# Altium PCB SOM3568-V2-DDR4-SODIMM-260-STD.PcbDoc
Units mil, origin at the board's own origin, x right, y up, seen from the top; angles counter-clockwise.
Board outline 6000 x 4000 mil, 4 copper layers (TOP, VCC, GND, BOTTOM), stack 28.8 mil thick; 1 components, 546 nets, 266 pads, 0 vias.
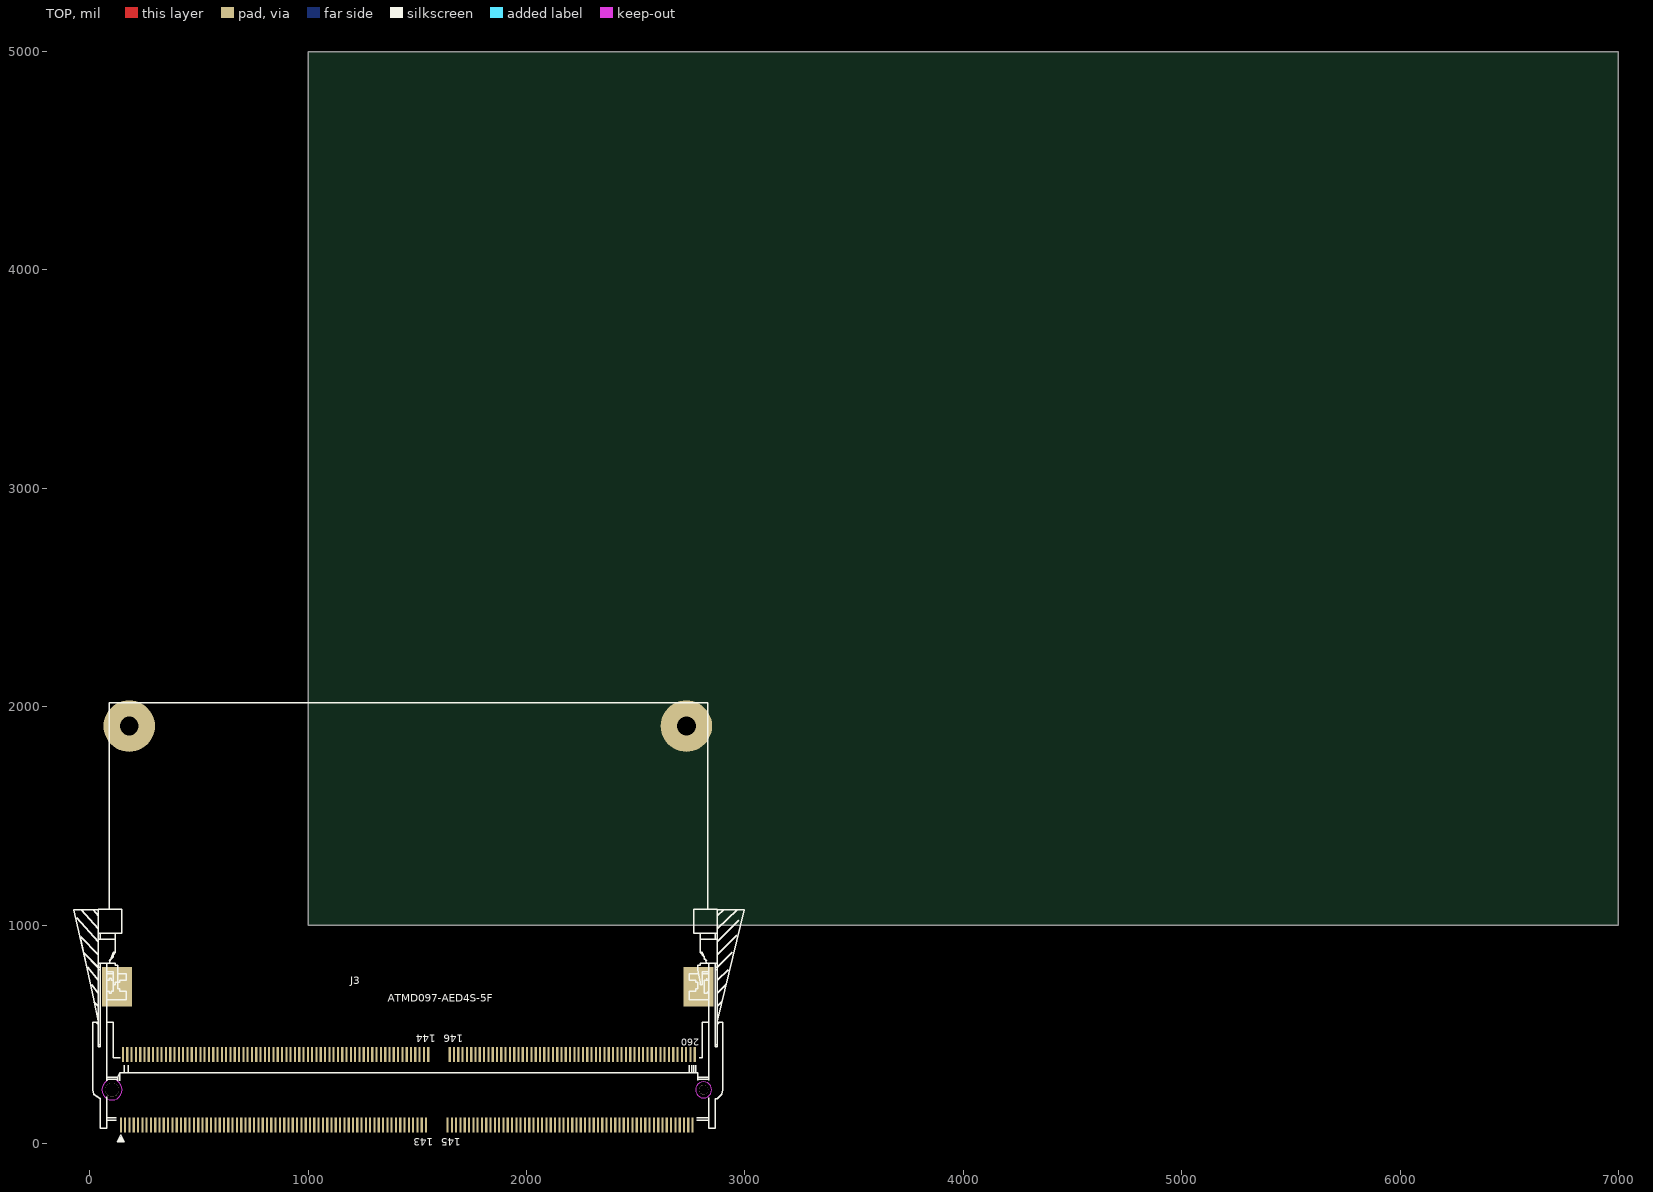
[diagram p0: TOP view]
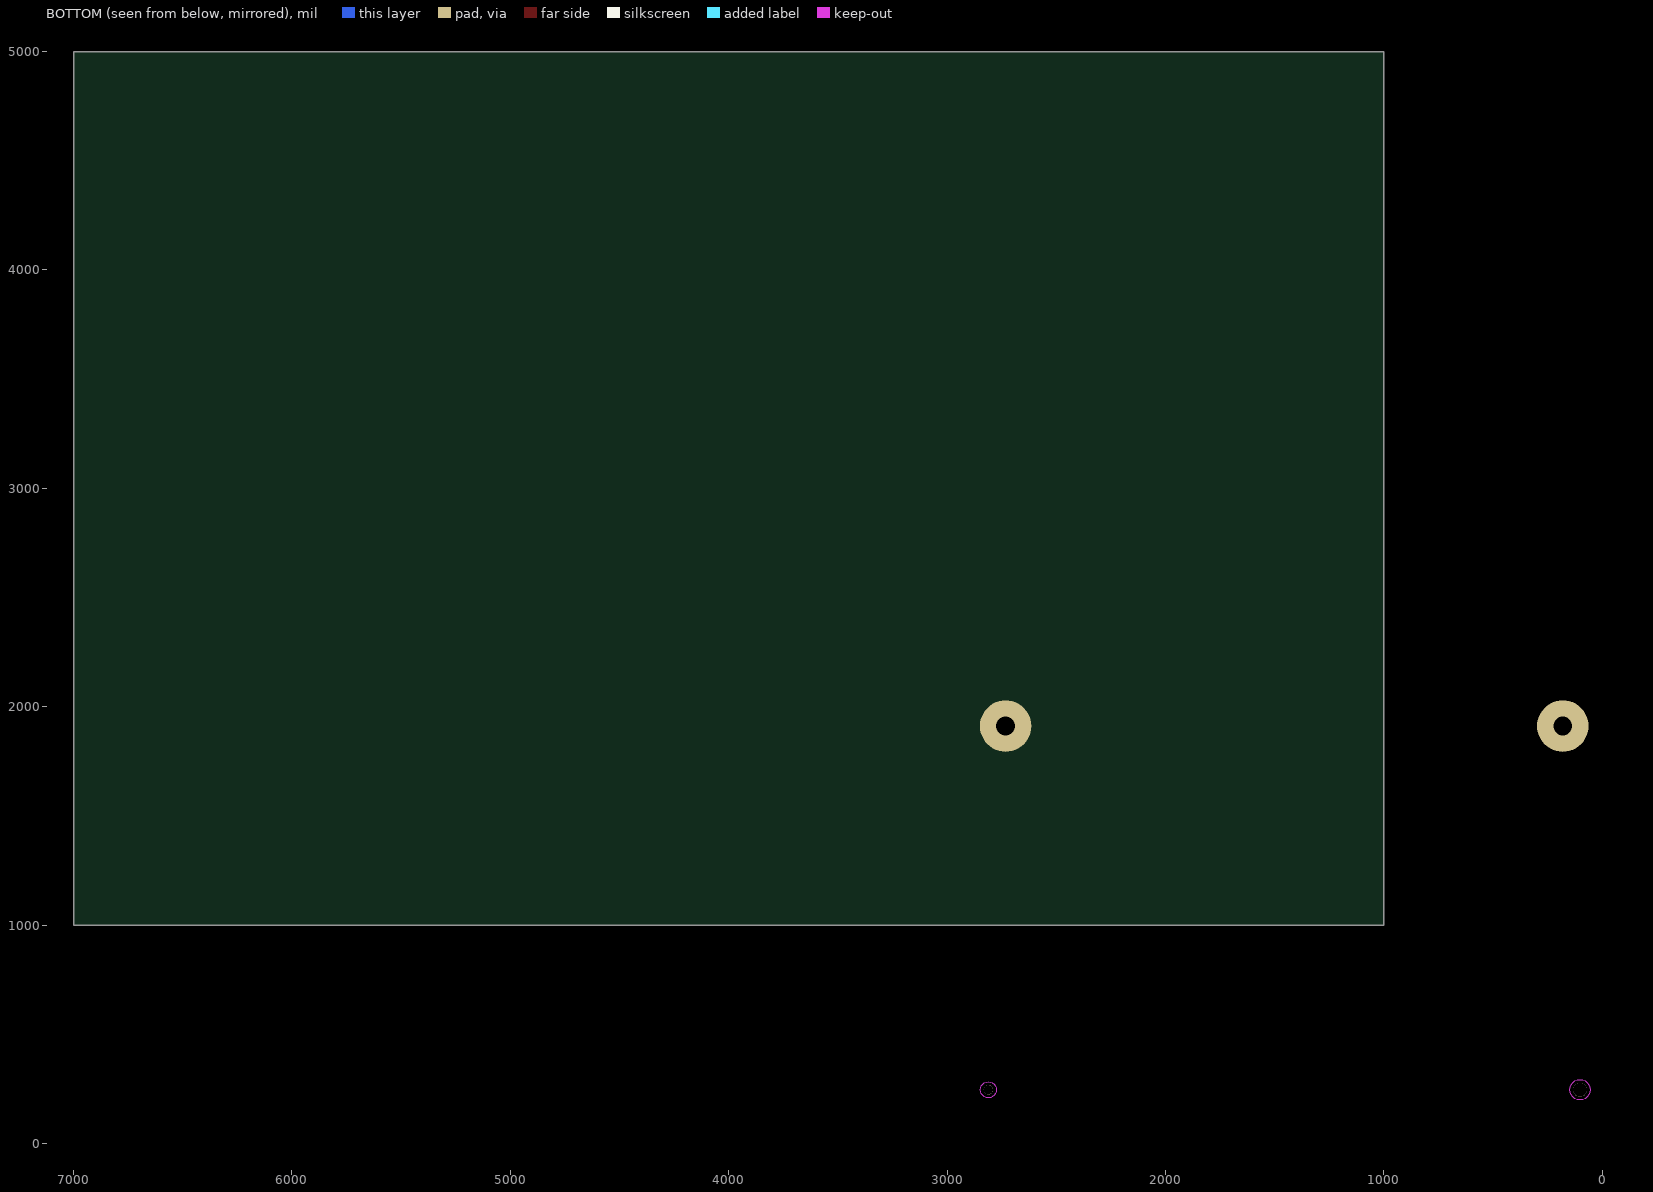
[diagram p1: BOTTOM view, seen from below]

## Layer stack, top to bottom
Top Solder: solder mask 0.4, Solder Resist, Dk 3.5
TOP: signal copper 1.2
Dielectric 1: core 8, FR-4, Dk 4.5
VCC: signal copper 1.2
Dielectric2: core 8, FR-4, Dk 4.5
GND: signal copper 1.2
Dielectric3: core 8, FR-4, Dk 4.5
BOTTOM: signal copper 1.2
Bottom Solder: solder mask 0.4, Solder Resist, Dk 3.5

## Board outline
1000,1000 7000,1000 7000,5000 1000,5000

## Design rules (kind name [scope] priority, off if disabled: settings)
Clearance [All] p1: gap=10 ignorepadtopadclearanceinfootprint=FALSE except(0: Arc-Hole Track-Hole SMDPad-Hole THPad-Hole Via-Hole Fill-Hole Poly-Hole Region-Hole Text-Hole)
DiffPairsRouting [All] p1: maxlimit=10 minlimit=10 mostfreqgap=10 toplayer_minwidth=15 toplayer_maxwidth=15 toplayer_prefwidth=15 midlayer1_minwidth=15 midlayer1_maxwidth=15 midlayer1_prefwidth=15 midlayer2_minwidth=15 midlayer2_maxwidth=15 midlayer2_prefwidth=15 bottomlayer_minwidth=15 bottomlayer_maxwidth=15 bottomlayer_prefwidth=15 maxuncoupledlength=500
PlaneConnect [All] p1: planeconnectstyle=Direct reliefexpansion=20 reliefentries=4 reliefconductorwidth=10 reliefairgap=10
PolygonConnect [All] p1: connectstyle=Direct reliefconductorwidth=10 reliefentries=4 polygonreliefangle="90 Angle" airgapwidth=10
RoutingVias [All] p1: holewidth=28 width=50 viastyle="Through Hole" minholewidth=28 minwidth=50 maxholewidth=28 maxwidth=50
SolderMaskExpansion [All] p1: expansion=4 istentingtop=FALSE
Width [All] p1: maxlimit=10 minlimit=10 preferedwidth=10 impedanceprofiledriven=TRUE minimp=0.000000 maximp=0.000000 favimp=99999999999999948800000000000000.000000
28 further rules are at their usual default settings.

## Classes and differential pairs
net class GND: GND
differential pair DIFFPAIR95: +VOR- -VOR+
differential pair DIFFPAIR98: +VON1 -VOP1
differential pair DIFFPAIR43: +USB3_OTG0_SSTXN -USB3_OTG0_SSTXP
differential pair DIFFPAIR49: +USB3_OTG0_SSRXN -USB3_OTG0_SSRXP
differential pair DIFFPAIR151: +USB3_OTG0_DM_ -USB3_OTG0_DP_
differential pair DIFFPAIR44: +USB3_OTG0_DM -USB3_OTG0_DP
differential pair DIFFPAIR111: +USB3_HOST1_SSTXN_ -USB3_HOST1_SSTXP_
differential pair DIFFPAIR41: +USB3_HOST1_SSTXN -USB3_HOST1_SSTXP
differential pair DIFFPAIR110: +USB3_HOST1_SSRXN_ -USB3_HOST1_SSRXP_
differential pair DIFFPAIR47: +USB3_HOST1_SSRXN -USB3_HOST1_SSRXP
differential pair DIFFPAIR108: +USB3_HOST1_DM_ -USB3_HOST1_DP_
differential pair DIFFPAIR45: +USB3_HOST1_DM -USB3_HOST1_DP
differential pair DIFFPAIR11: +USB2_HOST3_DM -USB2_HOST3_DP
differential pair DIFFPAIR109: +USB2_HOST2_DM_ -USB2_HOST2_DP_
differential pair DIFFPAIR71: +USB2_HOST2_DM -USB2_HOST2_DP
differential pair DIFFPAIR133: +RS485-A_ -RS485-B_
differential pair DIFFPAIR130: +RS485-A -RS485-B
differential pair DIFFPAIR129: +RS485_DM -RS485_DP
differential pair DIFFPAIR144: +RS232-RX_ -RS232-TX_
differential pair DIFFPAIR143: +RS232-RX -RS232-TX
differential pair DIFFPAIR117: +PHY1_MDI3- -PHY1_MDI3+
differential pair DIFFPAIR118: +PHY1_MDI2- -PHY1_MDI2+
differential pair DIFFPAIR119: +PHY1_MDI1- -PHY1_MDI1+
differential pair DIFFPAIR120: +PHY1_MDI0- -PHY1_MDI0+
differential pair DIFFPAIR76: +PHY0_MDI3- -PHY0_MDI3+
differential pair DIFFPAIR77: +PHY0_MDI2- -PHY0_MDI2+
differential pair DIFFPAIR78: +PHY0_MDI1- -PHY0_MDI1+
differential pair DIFFPAIR83: +PHY0_MDI0- -PHY0_MDI0+
differential pair DIFFPAIR145: +N69526109 -N69526111
differential pair DIFFPAIR102: +MIPI_CSI_RX_D3N -MIPI_CSI_RX_D3P
differential pair DIFFPAIR101: +MIPI_CSI_RX_D2N -MIPI_CSI_RX_D2P
differential pair DIFFPAIR100: +MIPI_CSI_RX_D1N -MIPI_CSI_RX_D1P
differential pair DIFFPAIR99: +MIPI_CSI_RX_D0N -MIPI_CSI_RX_D0P
differential pair DIFFPAIR147: +MIPI_CSI_RX_CLK1N -MIPI_CSI_RX_CLK1P
differential pair DIFFPAIR103: +MIPI_CSI_RX_CLK0N -MIPI_CSI_RX_CLK0P
differential pair DIFFPAIR107: +MIPI_CSI_D3N -MIPI_CSI_D3P
differential pair DIFFPAIR106: +MIPI_CSI_D2N -MIPI_CSI_D2P
differential pair DIFFPAIR105: +MIPI_CSI_D1N -MIPI_CSI_D1P
differential pair DIFFPAIR104: +MIPI_CSI_D0N -MIPI_CSI_D0P
differential pair DIFFPAIR146: +MIPI_CSI_CLK1N -MIPI_CSI_CLK1P
differential pair DIFFPAIR148: +MIPI_CSI_CLK0N -MIPI_CSI_CLK0P
differential pair DIFFPAIR150: +LVDS_TX0_D3N_ -LVDS_TX0_D3P_
differential pair DIFFPAIR149: +LVDS_TX0_D3N -LVDS_TX0_D3P
differential pair DIFFPAIR123: +LVDS_TX0_D2N_ -LVDS_TX0_D2P_
differential pair DIFFPAIR124: +LVDS_TX0_D2N -LVDS_TX0_D2P
differential pair DIFFPAIR125: +LVDS_TX0_D1N_ -LVDS_TX0_D1P_
differential pair DIFFPAIR126: +LVDS_TX0_D1N -LVDS_TX0_D1P
differential pair DIFFPAIR128: +LVDS_TX0_D0N_ -LVDS_TX0_D0P_
differential pair DIFFPAIR127: +LVDS_TX0_D0N -LVDS_TX0_D0P
differential pair DIFFPAIR122: +LVDS_TX0_CLKN_ -LVDS_TX0_CLKP_
differential pair DIFFPAIR121: +LVDS_TX0_CLKN -LVDS_TX0_CLKP
differential pair DIFFPAIR113: +LAN1_D- -LAN1_D+
differential pair DIFFPAIR114: +LAN1_C- -LAN1_C+
differential pair DIFFPAIR115: +LAN1_B- -LAN1_B+
differential pair DIFFPAIR116: +LAN1_A- -LAN1_A+
differential pair DIFFPAIR81: +LAN0_D- -LAN0_D+
differential pair DIFFPAIR80: +LAN0_C- -LAN0_C+
differential pair DIFFPAIR79: +LAN0_B- -LAN0_B+
differential pair DIFFPAIR82: +LAN0_A- -LAN0_A+
differential pair DIFFPAIR1: +HDMI_TX_D2N_ -HDMI_TX_D2P_
differential pair DIFFPAIR0: +HDMI_TX_D2N -HDMI_TX_D2P
differential pair DIFFPAIR2: +HDMI_TX_D1N_ -HDMI_TX_D1P_
differential pair DIFFPAIR3: +HDMI_TX_D1N -HDMI_TX_D1P
differential pair DIFFPAIR4: +HDMI_TX_D0N_ -HDMI_TX_D0P_
differential pair DIFFPAIR5: +HDMI_TX_D0N -HDMI_TX_D0P
differential pair DIFFPAIR6: +HDMI_TX_CLKN_ -HDMI_TX_CLKP_
differential pair DIFFPAIR7: +HDMI_TX_CLKN -HDMI_TX_CLKP
differential pair DIFFPAIR152: +CAN2H_ -CAN2L_
differential pair DIFFPAIR139: +CAN2H -CAN2L
differential pair DIFFPAIR142: +CAN2_RX_M0- -CAN2_TX_M0-
differential pair DIFFPAIR138: +CAN2_H -CAN2_L
differential pair DIFFPAIR135: +CAN1H_ -CAN1L_
differential pair DIFFPAIR136: +CAN1H -CAN1L
differential pair DIFFPAIR141: +CAN1_RX_M1_ -CAN1_TX_M1_
differential pair DIFFPAIR137: +CAN1_H -CAN1_L
differential pair DIFFPAIR134: +CAN0H_ -CAN0L_
differential pair DIFFPAIR132: +CAN0H -CAN0L
differential pair DIFFPAIR140: +CAN0_RX_M0_ -CAN0_TX_M0_
differential pair DIFFPAIR131: +CAN0_H -CAN0_L
differential pair DIFFPAIR112: +4G_DM -4G_DP

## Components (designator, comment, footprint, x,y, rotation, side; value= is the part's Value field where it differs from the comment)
J3 "ATMD097-AED4S-5F_5_DDR4-SODIMM-" SILKSCREEN_TOP 1460.77,1031.07 r0 top

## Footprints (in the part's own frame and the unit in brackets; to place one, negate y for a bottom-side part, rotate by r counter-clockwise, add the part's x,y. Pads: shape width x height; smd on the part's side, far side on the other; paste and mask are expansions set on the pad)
SILKSCREEN_TOP [mil] "SILKSCREEN_TOP"
  rect 9.84x68.9 smd: 1(-1318.41,-946.49) 2(-1308.57,-623.65) 3(-1298.73,-946.49) 4(-1288.88,-623.65) 5(-1279.04,-946.49) 6(-1269.2,-623.65) 7(-1259.36,-946.49) 8(-1249.51,-623.65) 9(-1239.67,-946.49) 10(-1229.83,-623.65) 11(-1219.99,-946.49) 12(-1210.14,-623.65) 13(-1200.3,-946.49) 14(-1190.46,-623.65) 15(-1180.62,-946.49) 16(-1170.77,-623.65) 17(-1160.93,-946.49) 18(-1151.09,-623.65) 19(-1141.25,-946.49) 20(-1131.4,-623.65) 21(-1121.56,-946.49) 22(-1111.72,-623.65) 23(-1101.88,-946.49) 24(-1092.03,-623.65) 25(-1082.19,-946.49) 26(-1072.35,-623.65) 27(-1062.51,-946.49) 28(-1052.66,-623.65) 29(-1042.82,-946.49) 30(-1032.98,-623.65) 31(-1023.14,-946.49) 32(-1013.29,-623.65) 33(-1003.45,-946.49) 34(-993.61,-623.65) 35(-983.77,-946.49) 36(-973.92,-623.65) 37(-964.08,-946.49) 38(-954.24,-623.65) 39(-944.4,-946.49) 40(-934.55,-623.65) 41(-924.71,-946.49) 42(-914.87,-623.65) 43(-905.03,-946.49) 44(-895.18,-623.65) 45(-885.34,-946.49) 46(-875.5,-623.65) 47(-865.66,-946.49) 48(-855.81,-623.65) 49(-845.97,-946.49) 50(-836.13,-623.65) 51(-826.29,-946.49) 52(-816.44,-623.65) 53(-806.6,-946.49) 54(-796.76,-623.65) 55(-786.92,-946.49) 56(-777.07,-623.65) 57(-767.23,-946.49) 58(-757.39,-623.65) 59(-747.54,-946.49) 60(-737.7,-623.65) 61(-727.86,-946.49) 62(-718.02,-623.65) 63(-708.17,-946.49) 64(-698.33,-623.65) 65(-688.49,-946.49) 66(-678.65,-623.65) 67(-668.8,-946.49) 68(-658.96,-623.65) 69(-649.12,-946.49) 70(-639.28,-623.65) 71(-629.43,-946.49) 72(-619.59,-623.65) 73(-609.75,-946.49) 74(-599.91,-623.65) 75(-590.06,-946.49) 76(-580.22,-623.65) 77(-570.38,-946.49) 78(-560.54,-623.65) 79(-550.69,-946.49) 80(-540.85,-623.65) 81(-531.01,-946.49) 82(-521.17,-623.65) 83(-511.32,-946.49) 84(-501.48,-623.65) 85(-491.64,-946.49) 86(-481.8,-623.65) 87(-471.95,-946.49) 88(-462.11,-623.65) 89(-452.27,-946.49) 90(-442.43,-623.65) 91(-432.58,-946.49) 92(-422.74,-623.65) 93(-412.9,-946.49) 94(-403.06,-623.65) 95(-393.21,-946.49) 96(-383.37,-623.65) 97(-373.53,-946.49) 98(-363.69,-623.65) 99(-353.84,-946.49) 100(-344,-623.65) 101(-334.16,-946.49) 102(-324.32,-623.65) 103(-314.47,-946.49) 104(-304.63,-623.65) 105(-294.79,-946.49) 106(-284.95,-623.65) 107(-275.1,-946.49) 108(-265.26,-623.65) 109(-255.42,-946.49) 110(-245.58,-623.65) 111(-235.73,-946.49) 112(-225.89,-623.65) 113(-216.05,-946.49) 114(-206.21,-623.65) 115(-196.36,-946.49) 116(-186.52,-623.65) 117(-176.68,-946.49) 118(-166.84,-623.65) 119(-156.99,-946.49) 120(-147.15,-623.65) 121(-137.31,-946.49) 122(-127.47,-623.65) 123(-117.62,-946.49) 124(-107.78,-623.65) 125(-97.94,-946.49) 126(-88.1,-623.65) 127(-78.25,-946.49) 128(-68.41,-623.65) 129(-58.57,-946.49) 130(-48.73,-623.65) 131(-38.88,-946.49) 132(-29.04,-623.65) 133(-19.2,-946.49) 134(-9.36,-623.65) 135(0.49,-946.49) 136(10.33,-623.65) 137(20.17,-946.49) 138(30.01,-623.65) 139(39.86,-946.49) 140(49.7,-623.65) 141(59.54,-946.49) 142(69.38,-623.65) 143(79.23,-946.49) 144(89.07,-623.65) 145(177.65,-946.49) 146(187.49,-623.65) 147(197.34,-946.49) 148(207.18,-623.65) 149(217.02,-946.49) 150(226.86,-623.65) 151(236.71,-946.49) 152(246.55,-623.65) 153(256.39,-946.49) 154(266.23,-623.65) 155(276.08,-946.49) 156(285.92,-623.65) 157(295.76,-946.49) 158(305.6,-623.65) 159(315.45,-946.49) 160(325.29,-623.65) 161(335.13,-946.49) 162(344.97,-623.65) 163(354.82,-946.49) 164(364.66,-623.65) 165(374.5,-946.49) 166(384.34,-623.65) 167(394.19,-946.49) 168(404.03,-623.65) 169(413.87,-946.49) 170(423.71,-623.65) 171(433.56,-946.49) 172(443.4,-623.65) 173(453.24,-946.49) 174(463.08,-623.65) 175(472.93,-946.49) 176(482.77,-623.65) 177(492.61,-946.49) 178(502.46,-623.65) 179(512.3,-946.49) 180(522.14,-623.65) 181(531.98,-946.49) 182(541.83,-623.65) 183(551.67,-946.49) 184(561.51,-623.65) 185(571.35,-946.49) 186(581.2,-623.65) 187(591.04,-946.49) 188(600.88,-623.65) 189(610.72,-946.49) 190(620.57,-623.65) 191(630.41,-946.49) 192(640.25,-623.65) 193(650.09,-946.49) 194(659.94,-623.65) 195(669.78,-946.49) 196(679.62,-623.65) 197(689.46,-946.49) 198(699.31,-623.65) 199(709.15,-946.49) 200(718.99,-623.65) 201(728.83,-946.49) 202(738.68,-623.65) 203(748.52,-946.49) 204(758.36,-623.65) 205(768.2,-946.49) 206(778.05,-623.65) 207(787.89,-946.49) 208(797.73,-623.65) 209(807.57,-946.49) 210(817.42,-623.65) 211(827.26,-946.49) 212(837.1,-623.65) 213(846.94,-946.49) 214(856.79,-623.65) 215(866.63,-946.49) 216(876.47,-623.65) 217(886.31,-946.49) 218(896.16,-623.65) 219(906,-946.49) 220(915.84,-623.65) 221(925.68,-946.49) 222(935.53,-623.65) 223(945.37,-946.49) 224(955.21,-623.65) 225(965.05,-946.49) 226(974.9,-623.65) 227(984.74,-946.49) 228(994.58,-623.65) 229(1004.42,-946.49) 230(1014.27,-623.65) 231(1024.11,-946.49) 232(1033.95,-623.65) 233(1043.79,-946.49) 234(1053.64,-623.65) 235(1063.48,-946.49) 236(1073.32,-623.65) 237(1083.16,-946.49) 238(1093.01,-623.65) 239(1102.85,-946.49) 240(1112.69,-623.65) 241(1122.53,-946.49) 242(1132.38,-623.65) 243(1142.22,-946.49) 244(1152.06,-623.65) 245(1161.9,-946.49) 246(1171.75,-623.65) 247(1181.59,-946.49) 248(1191.43,-623.65) 249(1201.27,-946.49) 250(1211.12,-623.65) 251(1220.96,-946.49) 252(1230.8,-623.65) 253(1240.64,-946.49) 254(1250.49,-623.65) 255(1260.33,-946.49) 256(1270.17,-623.65) 257(1280.01,-946.49) 258(1289.86,-623.65) 259(1299.7,-946.49) 260(1309.54,-623.65)
  rect 138x181 smd: N1(-1335.14,-312.63) N2(1326.27,-312.63)
  round 236.22 / inner round 141.73 / far side round 236.22 hole 86.61: N3(-1280.03,880.29) N4(1271.15,880.29)
  round 62.99 hole 62.99 unplated: ""(-1358.77,-785.07)
  round 43.31 hole 43.31 unplated: ""(1349.9,-785.07)
  Multi-Layer keep-out region: 1386.62,-785.07 1385.37,-775.56 1381.7,-766.7 1375.87,-759.1 1368.26,-753.26 1359.4,-749.59 1349.89,-748.34 1340.39,-749.59 1331.53,-753.26 1331.53,-753.26 1323.92,-759.1 1318.09,-766.7 1314.42,-775.56 1313.17,-785.07 1314.42,-794.57 1318.09,-803.43 1323.92,-811.04 1331.53,-816.88 1331.53,-816.88 1340.39,-820.54 1349.89,-821.8 1359.4,-820.54 1368.26,-816.88 1375.87,-811.04 1381.7,-803.43 1385.37,-794.57 1386.62,-785.07
  Multi-Layer keep-out region: -1312.11,-785.07 -1313.7,-772.99 -1318.36,-761.74 -1325.78,-752.08 -1335.44,-744.66 -1346.69,-740 -1358.77,-738.41 -1370.84,-740 -1382.09,-744.66 -1382.09,-744.66 -1391.76,-752.08 -1399.17,-761.74 -1403.83,-772.99 -1405.42,-785.07 -1403.83,-797.14 -1399.17,-808.39 -1391.76,-818.06 -1382.09,-825.47 -1382.09,-825.47 -1370.84,-830.13 -1358.77,-831.72 -1346.69,-830.13 -1335.44,-825.47 -1325.78,-818.06 -1318.36,-808.39 -1313.7,-797.14 -1312.11,-785.07
  silkscreen extent -1535,-1024 1536,987, body extent -1534,-987 1534,987, height 150

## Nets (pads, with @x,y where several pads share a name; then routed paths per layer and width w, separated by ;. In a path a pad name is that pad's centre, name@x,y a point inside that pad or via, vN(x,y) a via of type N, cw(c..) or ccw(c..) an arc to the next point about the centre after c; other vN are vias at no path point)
1PPS_: 
4G_DM: 
4G_DP: 
4G_LED_WANN#: 
4G_PWREN_H_GPIO0_D5: J3.11
ATGM332D_RX: 
ATGM332D_TX: 
BT_REG_ON: 
BT_REG_ON_H_GPIO3_A0: J3.71
BT_RST: 
BT_RST_L_GPIO4_C4: J3.140
BT_WAKE_HOST: 
BT_WAKE_HOST_H_GPIO3_A1: J3.67
CAM0_PDN: 
CAM0_RST: 
CAM1_PDN: 
CAM1_RST: 
CAM_CLKOUT0: J3.108
CAM_CLKOUT0_: 
CAM_CLKOUT1_: 
CAN0_H: 
CAN0_L: 
CAN0_RX_M0: J3.148
CAN0_RX_M0_: 
CAN0_STB_IO: 
CAN0_TX_M0: J3.146
CAN0_TX_M0_: 
CAN0H: 
CAN0H_: 
CAN0L: 
CAN0L_: 
CAN1_H: 
CAN1_L: 
CAN1_RX_M1: J3.136
CAN1_RX_M1_: 
CAN1_STB_IO: 
CAN1_TX_M1: J3.138
CAN1_TX_M1_: 
CAN1H: 
CAN1H_: 
CAN1L: 
CAN1L_: 
CAN2_H: 
CAN2_L: 
CAN2_RX_M0: J3.44
CAN2_RX_M0-: 
CAN2_RX_M0_: 
CAN2_STB_IO: 
CAN2_TX_M0: J3.46
CAN2_TX_M0-: 
CAN2_TX_M0_: 
CAN2H: 
CAN2H_: 
CAN2L: 
CAN2L_: 
CIF_CLKOUT_SOC: J3.52
DOG_GPIO0_C2: J3.124
ETH0_REFCLKO_25M: J3.228
ETH1_REFCLKO_25M_M0: J3.53
EXT_EN: J3.249
GMAC0_INT/PMEB_GPIO2_D2: J3.83
GMAC0_MCLKINOUT: J3.230
GMAC0_MDC: J3.232
GMAC0_MDIO: J3.234
GMAC0_RSTN_GPIO2_D3: J3.81
GMAC0_RXCLK: J3.223
GMAC0_RXD0: J3.222
GMAC0_RXD1: J3.224
GMAC0_RXD2: J3.219
GMAC0_RXD3: J3.221
GMAC0_RXDV_CRS: J3.226
GMAC0_TXCLK: J3.229
GMAC0_TXCLK_: 
GMAC0_TXD0: J3.216
GMAC0_TXD0_: 
GMAC0_TXD1: J3.218
GMAC0_TXD1_: 
GMAC0_TXD2: J3.225
GMAC0_TXD2_: 
GMAC0_TXD3: J3.227
GMAC0_TXD3_: 
GMAC0_TXEN: J3.220
GMAC0_TXEN_: 
GMAC1_INT/PMEB_GPIO3_A7: J3.55
GMAC1_MCLKINOUT_M1: J3.54
GMAC1_MDC_M1: J3.48
GMAC1_MDIO_M1: J3.50
GMAC1_RSTN_GPIO3_B5: J3.74
GMAC1_RXCLK_M1: J3.45
GMAC1_RXD0_M1: J3.34
GMAC1_RXD1_M1: J3.36
GMAC1_RXD2_M1: J3.41
GMAC1_RXD3_M1: J3.43
GMAC1_RXDV_CRS_M1: J3.38
GMAC1_TXCLK_M1: J3.39
GMAC1_TXCLK_M1_: 
GMAC1_TXD0_M1: J3.47
GMAC1_TXD0_M1_: 
GMAC1_TXD1_M1: J3.49
GMAC1_TXD1_M1_: 
GMAC1_TXD2_M1: J3.35
GMAC1_TXD2_M1_: 
GMAC1_TXD3_M1: J3.37
GMAC1_TXD3_M1_: 
GMAC1_TXEN_M1: J3.32
GMAC1_TXEN_M1_: 
GND: J3.15 J3.30 J3.31 J3.51 J3.56 J3.69 J3.84 J3.95 J3.106 J3.121 J3.145 J3.151 J3.158 J3.165 J3.180 J3.194 J3.195 J3.214 J3.217 J3.240 J3.254 J3.256 J3.258 J3.260 J3.N3 J3.N4
GND_EARTH: 
GND_IN: 
GPS_POWER_H_GPIO3_C2: J3.64
HDMI_TX_CEC_PORT: 
HDMI_TX_CLKN: J3.147
HDMI_TX_CLKN_: 
HDMI_TX_CLKP: J3.149
HDMI_TX_CLKP_: 
HDMI_TX_D0N: J3.155
HDMI_TX_D0N_: 
HDMI_TX_D0P: J3.153
HDMI_TX_D0P_: 
HDMI_TX_D1N: J3.159
HDMI_TX_D1N_: 
HDMI_TX_D1P: J3.157
HDMI_TX_D1P_: 
HDMI_TX_D2N: J3.163
HDMI_TX_D2N_: 
HDMI_TX_D2P: J3.161
HDMI_TX_D2P_: 
HDMI_TX_HPD_PORT: 
HDMI_TX_HPDIN: J3.143
HDMI_TXDDC_SCL_PORT: 
HDMI_TXDDC_SDA_PORT: 
HDMITX_CEC_M0: J3.89
HEATER_DIS_GPIO0_C6: J3.132
HOST_WAKE_BT: 
HOST_WAKE_BT_H_GPIO3_A2: J3.65
HP_SNS: J3.244
HPL_OUT: J3.242
HPR_OUT: J3.246
HW_ADDR1_GPIO2_D1: J3.85
HW_ADDR2_GPIO2_D0: J3.87
HW_ADDR3_GPIO3_C1: J3.66
HW_ADDR4_GPIO2_D7: J3.73
I2C3_SCL_M0: J3.156
I2C3_SDA_M0: J3.154
I2C4_SCL_M0: J3.42
I2C4_SDA_M0: J3.40
I2C5_SCL-HDMI: J3.93
I2C5_SCL_M0: J3.78
I2C5_SDA-HDMI: J3.91
I2C5_SDA_M0: J3.76
I2C_SCL_RTC: 
I2C_SDA_RTC: 
IR_PDN_H_GPIO1_D1: J3.12
IR_RST_L_GPIO1_D2: J3.14
ISO_5V: 
ISO_GND: 
KEY_REC: 
KEY_REST: 
LAN0_A+: 
LAN0_A-: 
LAN0_B+: 
LAN0_B-: 
LAN0_C+: 
LAN0_C-: 
LAN0_D+: 
LAN0_D-: 
LAN1_A+: 
LAN1_A-: 
LAN1_B+: 
LAN1_B-: 
LAN1_C+: 
LAN1_C-: 
LAN1_D+: 
LAN1_D-: 
LCD_RSTN_GPIO4_D2: J3.13
LCD_RSTN_GPIO4_D2_: 
LVDS_TX0_BL_EN: J3.134
LVDS_TX0_BL_EN_: 
LVDS_TX0_BL_PWM4: J3.126
LVDS_TX0_BL_PWM4_: 
LVDS_TX0_CLKN: J3.133
LVDS_TX0_CLKN_: 
LVDS_TX0_CLKP: J3.131
LVDS_TX0_CLKP_: 
LVDS_TX0_D0N: J3.141
LVDS_TX0_D0N_: 
LVDS_TX0_D0P: J3.139
LVDS_TX0_D0P_: 
LVDS_TX0_D1N: J3.137
LVDS_TX0_D1N_: 
LVDS_TX0_D1P: J3.135
LVDS_TX0_D1P_: 
LVDS_TX0_D2N: J3.129
LVDS_TX0_D2N_: 
LVDS_TX0_D2P: J3.127
LVDS_TX0_D2P_: 
LVDS_TX0_D3N: J3.125
LVDS_TX0_D3N_: 
LVDS_TX0_D3P: J3.123
LVDS_TX0_D3P_: 
M_POWER_MCU_PA4: 
M_RSTN: 
MCU_PA2: 
MCU_PA4: 
MCU_PA5: 
MIC1_INN: J3.250
MIC1_INP: J3.248
MIPI_CSI_CLK0N: 
MIPI_CSI_CLK0P: 
MIPI_CSI_CLK1N: 
MIPI_CSI_CLK1P: 
MIPI_CSI_D0N: 
MIPI_CSI_D0P: 
MIPI_CSI_D1N: 
MIPI_CSI_D1P: 
MIPI_CSI_D2N: 
MIPI_CSI_D2P: 
MIPI_CSI_D3N: 
MIPI_CSI_D3P: 
MIPI_CSI_RX_CLK0N: J3.103
MIPI_CSI_RX_CLK0P: J3.101
MIPI_CSI_RX_CLK1N: J3.99
MIPI_CSI_RX_CLK1P: J3.97
MIPI_CSI_RX_D0N: J3.119
MIPI_CSI_RX_D0P: J3.117
MIPI_CSI_RX_D1N: J3.115
MIPI_CSI_RX_D1P: J3.113
MIPI_CSI_RX_D2N: J3.111
MIPI_CSI_RX_D2P: J3.109
MIPI_CSI_RX_D3N: J3.107
MIPI_CSI_RX_D3P: J3.105
N17052705: 
N17052995: 
N17053074: 
N17053234: 
N17053342: 
N17053374: 
N17053434: 
N17846666: 
N68117689: 
N68120764: 
N68540703: 
N68563618: 
N68563661: 
N68600227: 
N68600229: 
N68600231: 
N68600309: 
N68610828: 
N68644173: 
N68784083: 
N68784087: 
N68821934: 
N68821936: 
N68886075: 
N69293889: 
N69293941: 
N69294259: 
N69294311: 
N69295042: 
N69295094: 
N69296779: 
N69296860: 
N69296862: 
N69298115: 
N69298251: 
N69298257: 
N69298259: 
N69299026: 
N69299038: 
N69299040: 
N69300875: 
N69301763: 
N69301799: 
N69301801: 
N69392291: 
N69401562: 
N69465614: 
N69474514: 
N69474785: 
N69483544: 
N69483663: 
N69483698: 
N69487454: 
N69488209: 
N69489713: 
N69490422: 
N69490516: 
N69524704: 
N69524710: 
N69524714: 
N69524758: 
N69526077: 
N69526079: 
N69526083: 
N69526085: 
N69526089: 
N69526093: 
N69526109: 
N69526111: 
N69526689: 
N69527850: 
N69527856: 
N69540624: 
N69541123: 
N69581826: 
N69581833: 
N69581843: 
N69586875: 
N69586917: 
N69587343: 
N69587346: 
N69587574: 
N69587581: 
N69602736: 
N69602838: 
N69604124: 
N69604170: 
N69605032: 
N69605064: 
N69619210: 
N69619220: 
N69619231: 
N69619239: 
N69619241: 
N69619283: 
N69619290: 
N69619323: 
N69619325: 
N69624375: 
N69701733: 
N69702712: 
NET_LED_GPIO4_C6: J3.144
NSD_CD: 
NTC_MCU_PA1: 
NTC_MCU_PA1_: 
NTC_SARADC_VIN3: J3.5
PA_GND: 
PE: 
PHY0_CLKOUT125: 
PHY0_G_LED-: 
PHY0_LED0/CFG_EXT: 
PHY0_LED1/CFG_LDO0: 
PHY0_LED2/CFG_LDO1: 
PHY0_MDI0+: 
PHY0_MDI0-: 
PHY0_MDI1+: 
PHY0_MDI1-: 
PHY0_MDI2+: 
PHY0_MDI2-: 
PHY0_MDI3+: 
PHY0_MDI3-: 
PHY0_REG_OUT: 
PHY0_RSTN: 
PHY0_RXCLK/PHYAD1: 
PHY0_RXD0/RXDLY: 
PHY0_RXD1/TXDLY: 
PHY0_RXD2/PLLOFF: 
PHY0_RXD3/PHYAD0: 
PHY0_RXDV/PHYAD2: 
PHY0_XTALIN: 
PHY0_XTALOUT: 
PHY0_Y_LED+: 
PHY1_CLKOUT125: 
PHY1_G_LED-: 
PHY1_LED0/CFG_EXT: 
PHY1_LED1/CFG_LDO0: 
PHY1_LED2/CFG_LDO1: 
PHY1_MDI0+: 
PHY1_MDI0-: 
PHY1_MDI1+: 
PHY1_MDI1-: 
PHY1_MDI2+: 
PHY1_MDI2-: 
PHY1_MDI3+: 
PHY1_MDI3-: 
PHY1_REG_OUT: 
PHY1_RSTN: 
PHY1_RXCLK/PHYAD1: 
PHY1_RXD0/RXDLY: 
PHY1_RXD1/TXDLY: 
PHY1_RXD2/PLLOFF: 
PHY1_RXD3/PHYAD0: 
PHY1_RXDV/PHYAD2: 
PHY1_XTALIN: 
PHY1_XTALOUT: 
PHY1_Y_LED+: 
RGB_PDN_H_GPIO1_D3: J3.18
RGB_RST_H_GPIO1_D4: J3.20
RK809-CLK32K: J3.247
RK809_PWRON: J3.251
RK809_VDC: J3.252
RS232-RX: 
RS232-RX_: 
RS232-TX: 
RS232-TX_: 
RS485-A: 
RS485-A_: 
RS485-B: 
RS485-B_: 
RS485_DIR: 
RS485_DIR_GPIO3_C3: J3.62
RS485_DM: 
RS485_DP: 
RSET0: 
RSET1: 
RTCIC_32KOUT: 
SARADC_VIN0_KEY/RECOVERY: J3.1
SCL_CAM: 
SD_CLK: 
SD_CMD: 
SD_D0: 
SD_D1: 
SD_D2: 
SD_D3: 
SDA_CAM: 
SDMMC0_CLK: J3.206
SDMMC0_CMD: J3.204
SDMMC0_D0: J3.196
SDMMC0_D1: J3.198
SDMMC0_D2: J3.200
SDMMC0_D3: J3.202
SDMMC0_DET_L: J3.208
SDMMC2_CLK_M0: J3.27
SDMMC2_CMD_M0: J3.25
SDMMC2_D0_M0: J3.17
SDMMC2_D1_M0: J3.19
SDMMC2_D2_M0: J3.21
SDMMC2_D3_M0: J3.23
SIM_CLK: 
SIM_DATA: 
SIM_RST: 
SPK_5V: 
SPK_CTL_H_GPIO3_A5: J3.59
SPK_MUTE_H_GPIO3_A4: J3.61
SYS_LED_GPIO4_C5: J3.142
SYS_RESETN: J3.235
TP_INT: 
TP_INT_L_GPIO0_B5: J3.150
TP_RST: 
TP_RST_L_GPIO0_B6: J3.152
TP_SCL: 
TP_SDA: 
TYPEC_CC1: 
TYPEC_CC2: 
UART2_RX_M0: J3.116
UART2_RX_M0_: 
UART2_TX_M0: J3.118
UART2_TX_M0_: 
UART3_RX_M1: J3.68
UART3_RX_M1_: 
UART3_TX_M1: J3.70
UART3_TX_M1_: 
UART4_RX_M1: J3.82
UART4_TX_M1: J3.80
UART7_RX_M1: J3.58
UART7_RX_M1_: 
UART7_TX_M1: J3.60
UART7_TX_M1_: 
UART8_CTSN_M0: J3.233
UART8_RTSN_M0: J3.231
UART8_RX_M0: J3.238
UART8_TX_M0: J3.236
USB2_HOST2_DM: J3.28
USB2_HOST2_DM_: 
USB2_HOST2_DP: J3.26
USB2_HOST2_DP_: 
USB2_HOST2_PWREN_H_GPIO0_A6: J3.110
USB2_HOST3_DM: J3.24
USB2_HOST3_DP: J3.22
USB3_HOST1_DM: J3.169
USB3_HOST1_DM_: 
USB3_HOST1_DP: J3.167
USB3_HOST1_DP_: 
USB3_HOST1_PWREN_H_GPIO0_D4: J3.9
USB3_HOST1_SSRXN: J3.175
USB3_HOST1_SSRXN_: 
USB3_HOST1_SSRXP: J3.177
USB3_HOST1_SSRXP_: 
USB3_HOST1_SSTXN: J3.171
USB3_HOST1_SSTXN_: 
USB3_HOST1_SSTXP: J3.173
USB3_HOST1_SSTXP_: 
USB3_OTG0_DM: J3.189
USB3_OTG0_DM_: 
USB3_OTG0_DP: J3.187
USB3_OTG0_DP_: 
USB3_OTG0_ID: J3.193
USB3_OTG0_SSRXN: J3.183
USB3_OTG0_SSRXP: J3.185
USB3_OTG0_SSTXN: J3.179
USB3_OTG0_SSTXP: J3.181
USB3_OTG0_VBUSDET: J3.191
USB_OTG_PWREN_H_GPIO0_A5: J3.212
USER_LED1_GPIO0_C5: J3.130
USER_LED2_GPIO1_D0: J3.10
VBAT_GPS_3V3: 
VBAT_RTC: 
VBAT_WL_1T1R: 
VCC1V2_DVP: 
VCC1V3_DVP: 
VCC1V8_DVP: 
VCC2V8_DVP: 
VCC3V3_PHY0: 
VCC3V3_PHY1: 
VCC3V3_SD: J3.210
VCC5V: 
VCC5V0_M: J3.253 J3.255 J3.257 J3.259
VCC5V0_SYS: 
VCC5V0_USB_HOST1: 
VCC5V0_USB_HOST2: 
VCC5V0_USB_OTG0: 
VCC5V_HDMI_TX: 
VCC12V_DC_IN: 
VCC12V_DCIN: 
VCC12V_OUT: 
VCC_1V8: J3.237
VCC_3V3: J3.245
VCC_3V3_ON: 
VCC_3V8: 
VCC_485: 
VCC_SIM: 
VCCIO_PHY0: 
VCCIO_PHY1: 
VCCIO_WL: 
VDD10_PHY0: 
VDD10_PHY1: 
VDD_3V3: 
VDD_LCD_3V3: 
VDD_RTC: 
VON1: 
VOP1: 
VOR+: 
VOR-: 
WIFI1T1R_CLK: 
WIFI1T1R_CMD: 
WIFI1T1R_D0: 
WIFI1T1R_D1: 
WIFI1T1R_D2: 
WIFI1T1R_D3: 
WIFI1T1R_XTAL_IN: 
WIFI1T1R_XTAL_OUT: 
WIFI_PWREN_L_GPIO0_B7: J3.114
WIFI_REG_ON_H_GPIO3_D5: J3.33
WIFI_WAKE_HOST_H_GPIO3_D4: J3.29
WIFIBT_32KIN_1T1R: 
pads on no net: J3. J3.2 J3.3 J3.4 J3.6 J3.7 J3.8 J3.16 J3.57 J3.63 J3.72 J3.75 J3.77 J3.79 J3.86 J3.88 J3.90 J3.92 J3.94 J3.96 J3.98 J3.100 J3.102 J3.104 J3.112 J3.120 J3.122 J3.128 J3.160 J3.162 J3.164 J3.166 J3.168 J3.170 J3.172 J3.174 J3.176 J3.178 J3.182 J3.184 J3.186 J3.188 J3.190 J3.192 J3.197 J3.199 J3.201 J3.203 J3.205 J3.207 J3.209 J3.211 J3.213 J3.215 J3.239 J3.241 J3.243 J3.N1 J3.N2

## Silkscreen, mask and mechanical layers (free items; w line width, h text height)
DRAWING_ORIGIN:
  lines w1: -25,0 25,0 ; 0,-25 0,25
